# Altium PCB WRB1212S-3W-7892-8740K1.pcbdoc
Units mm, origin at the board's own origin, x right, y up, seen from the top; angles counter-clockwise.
Board outline 23.7 x 14.8 mm, 2 copper layers (Top Layer, Bottom Layer), stack 0.78 mm thick; 26 components, 17 nets, 70 pads, 31 vias.
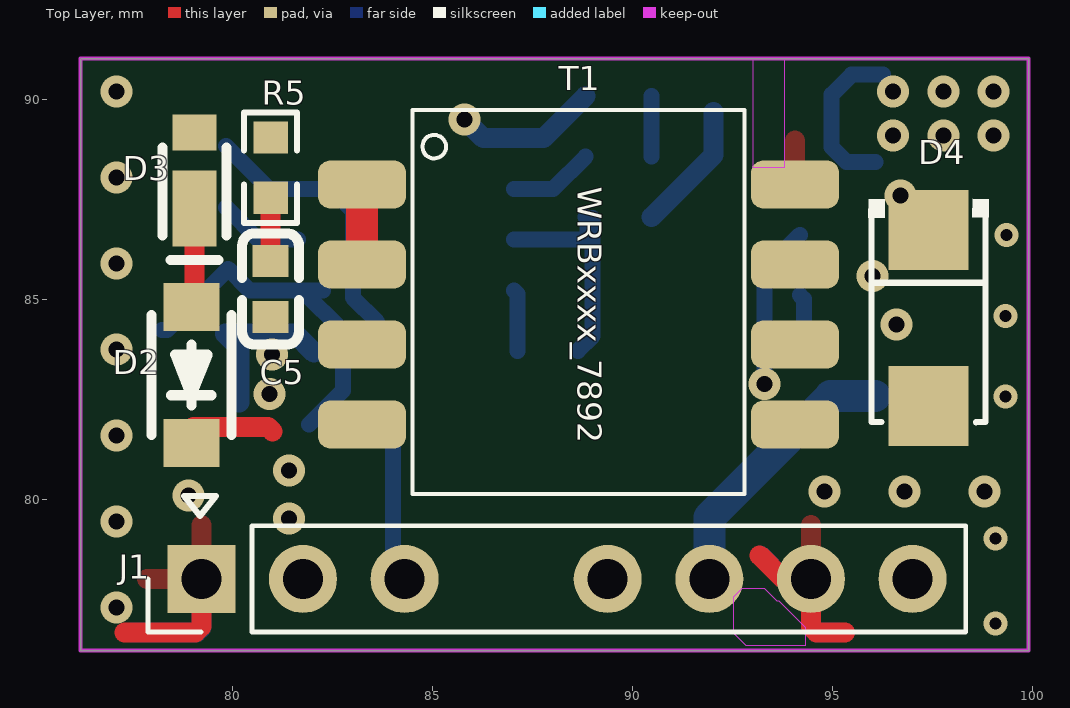
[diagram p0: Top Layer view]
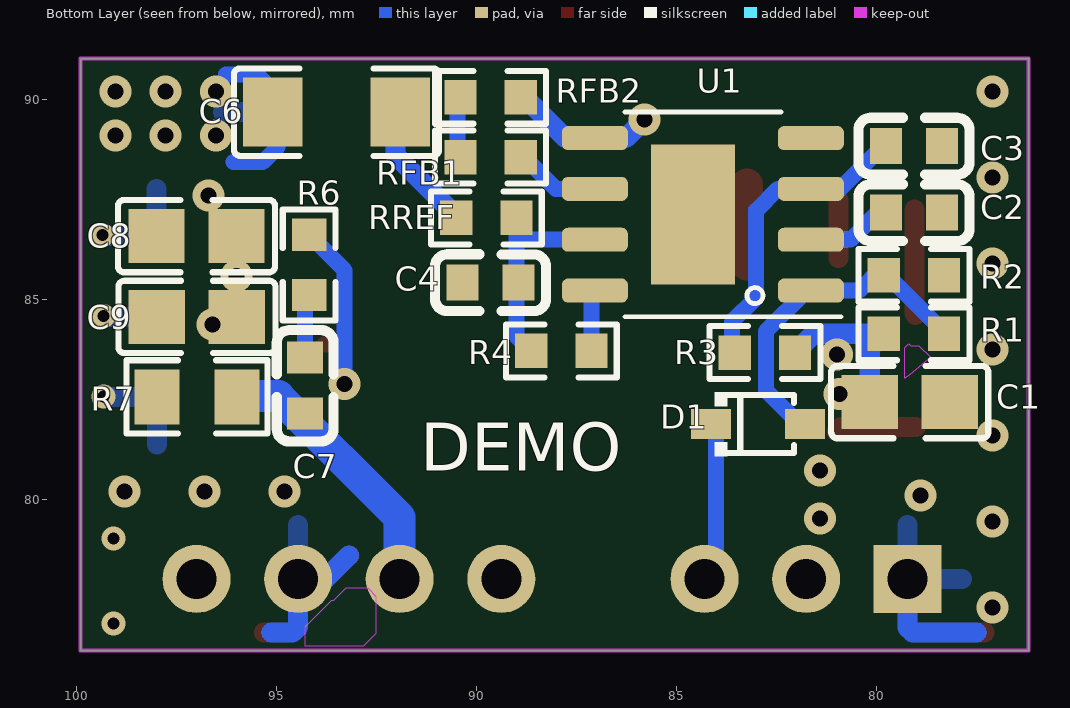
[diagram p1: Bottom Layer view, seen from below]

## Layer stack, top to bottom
Top Solder Mask Layer: solder mask 0.01, Dk 3.3
Top Layer: signal copper 0.035
Dielectric1: surface 0.71, FR4, Dk 4.5
Bottom Layer: signal copper 0.035
Bottom Solder Mask Layer: solder mask 0.01, Dk 3.3

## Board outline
76.2,91.02 99.9,91.02 99.9,76.22 76.2,76.22

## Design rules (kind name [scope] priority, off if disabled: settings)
BoardOutlineClearance safeClearance [All] p0: genericclearance=0.254 ignorepadtopadclearanceinfootprint=FALSE except(0: Arc-SplitContinuation Track-SplitContinuation SMDPad-SplitContinuation THPad-SplitContinuation Via-SplitContinuation Fill-SplitContinuation Poly-SplitContinuation Region-SplitContinuation Text-SplitContinuation)
BoardOutlineClearance Plane_innerPlane [All] p0: genericclearance=0.254 ignorepadtopadclearanceinfootprint=FALSE except(0: Arc-SplitContinuation Track-SplitContinuation SMDPad-SplitContinuation THPad-SplitContinuation Via-SplitContinuation Fill-SplitContinuation Poly-SplitContinuation Region-SplitContinuation Text-SplitContinuation)
BoardOutlineClearance Copper_CopperRegion [All] p0: genericclearance=0.254 ignorepadtopadclearanceinfootprint=FALSE except(0: Arc-SplitContinuation Track-SplitContinuation SMDPad-SplitContinuation THPad-SplitContinuation Via-SplitContinuation Fill-SplitContinuation Poly-SplitContinuation Region-SplitContinuation Text-SplitContinuation)
BoardOutlineClearance Copper_CopperRegion1 [All] p0: genericclearance=0.254 ignorepadtopadclearanceinfootprint=FALSE except(0: Arc-SplitContinuation Track-SplitContinuation SMDPad-SplitContinuation THPad-SplitContinuation Via-SplitContinuation Fill-SplitContinuation Poly-SplitContinuation Region-SplitContinuation Text-SplitContinuation)
BoardOutlineClearance Copper_CopperRegion2 [All] p0: genericclearance=0.254 ignorepadtopadclearanceinfootprint=FALSE except(0: Arc-SplitContinuation Track-SplitContinuation SMDPad-SplitContinuation THPad-SplitContinuation Via-SplitContinuation Fill-SplitContinuation Poly-SplitContinuation Region-SplitContinuation Text-SplitContinuation)
BoardOutlineClearance Copper_CopperRegion3 [All] p0: genericclearance=0.254 ignorepadtopadclearanceinfootprint=FALSE except(0: Arc-SplitContinuation Track-SplitContinuation SMDPad-SplitContinuation THPad-SplitContinuation Via-SplitContinuation Fill-SplitContinuation Poly-SplitContinuation Region-SplitContinuation Text-SplitContinuation)
BoardOutlineClearance Copper_CopperRegion4 [All] p0: genericclearance=0.254 ignorepadtopadclearanceinfootprint=FALSE except(0: Arc-SplitContinuation Track-SplitContinuation SMDPad-SplitContinuation THPad-SplitContinuation Via-SplitContinuation Fill-SplitContinuation Poly-SplitContinuation Region-SplitContinuation Text-SplitContinuation)
BoardOutlineClearance Copper_CopperRegion5 [All] p0: genericclearance=0.254 ignorepadtopadclearanceinfootprint=FALSE except(0: Arc-SplitContinuation Track-SplitContinuation SMDPad-SplitContinuation THPad-SplitContinuation Via-SplitContinuation Fill-SplitContinuation Poly-SplitContinuation Region-SplitContinuation Text-SplitContinuation)
BoardOutlineClearance Copper_CopperRegion6 [All] p0: genericclearance=0.254 ignorepadtopadclearanceinfootprint=FALSE except(0: Arc-SplitContinuation Track-SplitContinuation SMDPad-SplitContinuation THPad-SplitContinuation Via-SplitContinuation Fill-SplitContinuation Poly-SplitContinuation Region-SplitContinuation Text-SplitContinuation)
BoardOutlineClearance Copper_CopperRegion7 [All] p0: genericclearance=0.254 ignorepadtopadclearanceinfootprint=FALSE except(0: Arc-SplitContinuation Track-SplitContinuation SMDPad-SplitContinuation THPad-SplitContinuation Via-SplitContinuation Fill-SplitContinuation Poly-SplitContinuation Region-SplitContinuation Text-SplitContinuation)
BoardOutlineClearance Copper_CopperRegion8 [All] p0: genericclearance=0.254 ignorepadtopadclearanceinfootprint=FALSE except(0: Arc-SplitContinuation Track-SplitContinuation SMDPad-SplitContinuation THPad-SplitContinuation Via-SplitContinuation Fill-SplitContinuation Poly-SplitContinuation Region-SplitContinuation Text-SplitContinuation)
BoardOutlineClearance Copper_CopperRegion9 [All] p0: genericclearance=0.254 ignorepadtopadclearanceinfootprint=FALSE except(0: Arc-SplitContinuation Track-SplitContinuation SMDPad-SplitContinuation THPad-SplitContinuation Via-SplitContinuation Fill-SplitContinuation Poly-SplitContinuation Region-SplitContinuation Text-SplitContinuation)
BoardOutlineClearance Copper_CopperRegion10 [All] p0: genericclearance=0.254 ignorepadtopadclearanceinfootprint=FALSE except(0: Arc-SplitContinuation Track-SplitContinuation SMDPad-SplitContinuation THPad-SplitContinuation Via-SplitContinuation Fill-SplitContinuation Poly-SplitContinuation Region-SplitContinuation Text-SplitContinuation)
BoardOutlineClearance Copper_CopperRegion11 [All] p0: genericclearance=0.254 ignorepadtopadclearanceinfootprint=FALSE except(0: Arc-SplitContinuation Track-SplitContinuation SMDPad-SplitContinuation THPad-SplitContinuation Via-SplitContinuation Fill-SplitContinuation Poly-SplitContinuation Region-SplitContinuation Text-SplitContinuation)
BoardOutlineClearance Copper_CopperRegion12 [All] p0: genericclearance=0.254 ignorepadtopadclearanceinfootprint=FALSE except(0: Arc-SplitContinuation Track-SplitContinuation SMDPad-SplitContinuation THPad-SplitContinuation Via-SplitContinuation Fill-SplitContinuation Poly-SplitContinuation Region-SplitContinuation Text-SplitContinuation)
BoardOutlineClearance Copper_CopperRegion13 [All] p0: genericclearance=0.254 ignorepadtopadclearanceinfootprint=FALSE except(0: Arc-SplitContinuation Track-SplitContinuation SMDPad-SplitContinuation THPad-SplitContinuation Via-SplitContinuation Fill-SplitContinuation Poly-SplitContinuation Region-SplitContinuation Text-SplitContinuation)
BoardOutlineClearance otherClearance [All] p0: genericclearance=0.254 ignorepadtopadclearanceinfootprint=FALSE except(0: Arc-SplitContinuation Track-SplitContinuation SMDPad-SplitContinuation THPad-SplitContinuation Via-SplitContinuation Fill-SplitContinuation Poly-SplitContinuation Region-SplitContinuation Text-SplitContinuation)
Clearance safeClearance [All] p1: gap=0.178 ignorepadtopadclearanceinfootprint=FALSE
Clearance Plane_innerPlane [All] p1: gap=0.178 ignorepadtopadclearanceinfootprint=FALSE
Clearance Copper_CopperRegion [All] p1: gap=0.178 ignorepadtopadclearanceinfootprint=FALSE
Clearance Copper_CopperRegion1 [All] p1: gap=0.178 ignorepadtopadclearanceinfootprint=FALSE
Clearance Copper_CopperRegion2 [All] p1: gap=0.178 ignorepadtopadclearanceinfootprint=FALSE
Clearance Copper_CopperRegion3 [All] p1: gap=0.178 ignorepadtopadclearanceinfootprint=FALSE
Clearance Copper_CopperRegion4 [All] p1: gap=0.178 ignorepadtopadclearanceinfootprint=FALSE
Clearance Copper_CopperRegion5 [All] p1: gap=0.178 ignorepadtopadclearanceinfootprint=FALSE
Clearance Copper_CopperRegion6 [All] p1: gap=0.178 ignorepadtopadclearanceinfootprint=FALSE
Clearance Copper_CopperRegion7 [All] p1: gap=0.178 ignorepadtopadclearanceinfootprint=FALSE
Clearance Copper_CopperRegion8 [All] p1: gap=0.178 ignorepadtopadclearanceinfootprint=FALSE
Clearance Copper_CopperRegion9 [All] p1: gap=0.178 ignorepadtopadclearanceinfootprint=FALSE
Clearance Copper_CopperRegion10 [All] p1: gap=0.178 ignorepadtopadclearanceinfootprint=FALSE
Clearance Copper_CopperRegion11 [All] p1: gap=0.178 ignorepadtopadclearanceinfootprint=FALSE
Clearance Copper_CopperRegion12 [All] p1: gap=0.178 ignorepadtopadclearanceinfootprint=FALSE
Clearance Copper_CopperRegion13 [All] p1: gap=0.178 ignorepadtopadclearanceinfootprint=FALSE
Clearance otherClearance [All] p1: gap=0.178 ignorepadtopadclearanceinfootprint=FALSE
DiffPairsRouting differentialPair [All] p1: maxuncoupledlength=10 minlimit=5.9843 maxlimit=Infinity mostfreqgap=5.9843 toplayer_minwidth=5 toplayer_prefwidth=10 toplayer_maxwidth=100 bottomlayer_minwidth=5 bottomlayer_prefwidth=10 bottomlayer_maxwidth=100
PasteMaskExpansion Common [All] p1: expansion=0
PlaneConnect innerPlane [All] p1: planeconnectstyle=Relief reliefexpansion=0.508 reliefentries=4 reliefconductorwidth=0.254 reliefairgap=0.254
PolygonConnect CopperRegion [All] p1: connectstyle=Relief reliefentries=4 reliefconductorwidth=19.685 polygonreliefangle="90 Angle" airgapwidth=19.685
PolygonConnect CopperRegion1 [All] p1: connectstyle=Relief reliefentries=4 reliefconductorwidth=0 polygonreliefangle="90 Angle" airgapwidth=0.9843
PolygonConnect CopperRegion2 [All] p1: connectstyle=Direct reliefentries=4 reliefconductorwidth=10 polygonreliefangle="90 Angle" airgapwidth=10
PolygonConnect CopperRegion3 [All] p1: connectstyle=Relief reliefentries=4 reliefconductorwidth=19.685 polygonreliefangle="90 Angle" airgapwidth=19.685
PolygonConnect CopperRegion4 [All] p1: connectstyle=Direct reliefentries=4 reliefconductorwidth=10 polygonreliefangle="90 Angle" airgapwidth=10
PolygonConnect CopperRegion5 [All] p1: connectstyle=Direct reliefentries=4 reliefconductorwidth=10 polygonreliefangle="90 Angle" airgapwidth=10
PolygonConnect CopperRegion6 [All] p1: connectstyle=Direct reliefentries=4 reliefconductorwidth=10 polygonreliefangle="90 Angle" airgapwidth=10
PolygonConnect CopperRegion7 [All] p1: connectstyle=Direct reliefentries=4 reliefconductorwidth=10 polygonreliefangle="90 Angle" airgapwidth=10
PolygonConnect CopperRegion8 [All] p1: connectstyle=Direct reliefentries=4 reliefconductorwidth=10 polygonreliefangle="90 Angle" airgapwidth=10
PolygonConnect CopperRegion9 [All] p1: connectstyle=Relief reliefentries=4 reliefconductorwidth=19.685 polygonreliefangle="90 Angle" airgapwidth=19.685
PolygonConnect CopperRegion10 [All] p1: connectstyle=Direct reliefentries=4 reliefconductorwidth=10 polygonreliefangle="90 Angle" airgapwidth=10
PolygonConnect CopperRegion11 [All] p1: connectstyle=Relief reliefentries=4 reliefconductorwidth=19.685 polygonreliefangle="90 Angle" airgapwidth=19.685
PolygonConnect CopperRegion12 [All] p1: connectstyle=Direct reliefentries=4 reliefconductorwidth=10 polygonreliefangle="90 Angle" airgapwidth=10
PolygonConnect CopperRegion13 [All] p1: connectstyle=Direct reliefentries=4 reliefconductorwidth=10 polygonreliefangle="90 Angle" airgapwidth=10
RoutingVias viaSize [All] p1: viastyle="Through Hole" holewidth=12.0078 minholewidth=11.811 maxholewidth=236.1812 width=12.0078 minwidth=11.811 maxwidth=236.1812
SolderMaskExpansion Common [All] p1: useseparateexpansions=TRUE expansion=0 expansionbottom=0
Width trackWidth [All] p1: maxlimit=100 minlimit=5 preferedwidth=10

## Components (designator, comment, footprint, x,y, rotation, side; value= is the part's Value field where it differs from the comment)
C1 "" C0805 79.17,82.43 r180 bottom
C2 "" C0603 79.065,87.165 r0 bottom
C3 "" C0603 79.065,88.83 r180 bottom
C4 "" C0603 89.65,85.416 r180 bottom
C5 "" C0603 80.95,85.26 r270 top
C6 "" C1206 93.5,89.68 r180 bottom
C7 "" C0603 94.285,82.84 r270 bottom
C8 "" C0805 97,86.58 r0 bottom
C9 "" C0805 96.99,84.56 r0 bottom
D1 "" SOD-323_L1.8-W1.3-LS2.5-RD 82.96,81.88 r180 bottom
D2 "" SOD-123_L2.8-W1.8-LS3.9-FD 78.97,83.11 r270 top
D3 "" SOD-323HE_L1.9-W1.3-LS2.5-RD 79.05,88.22 r90 top
D4 "" SMA_L4.3-W2.6-LS5.2-RD 97.4,84.53 r270 top
J1 "" ? 79.22,78.01 r90 top
R1 "" R0603 79.065,84.137 r0 bottom
R2 "" R0603 79.065,85.601 r0 bottom
R3 "" R0603 82.79,83.67 r180 bottom
R4 "" R0603 87.88,83.71 r180 bottom
R5 "" R0603 80.95,88.29 r90 top
R6 "" R0603 94.185,85.86 r90 bottom
R7 "" R0805 96.99,82.56 r0 bottom
RFB1 "" R0603 89.65,88.556 r180 bottom
RFB2 "" R0603 89.65,90.05 r0 bottom
RREF "" R0603 89.755,87.036 r180 bottom
T1 "" "coileasy:SMD-8P, 11.55x9.6, ER9.5 4+4" 88.652,84.93 r0 top
U1 "CMP7892" coileasy:ESOP-8 84.34,87.125 r0 bottom

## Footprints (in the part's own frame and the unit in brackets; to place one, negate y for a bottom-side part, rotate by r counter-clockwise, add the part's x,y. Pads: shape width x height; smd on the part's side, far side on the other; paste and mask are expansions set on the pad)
C0603 [mm]
  rect 0.8x0.9 smd: 1(-0.7,0) 2(0.7,0)
  silkscreen extent -1.39,-0.71 1.39,0.71
C0805 [mm]
  rect 1.41x1.35 smd: 1(-1,0) 2(1,0)
  silkscreen extent -1.96,-0.9 1.96,0.9
C1206 [mm]
  rect 1.485x1.728 smd: 1(-1.593,0) 2(1.593,0)
  silkscreen extent -2.56,-1.09 2.56,1.09
coileasy:ESOP-8 [mm]
  rrect50% 1.65x0.6 smd: 1(-2.7,1.905) 2(-2.7,0.635) 3(-2.7,-0.635) 4(-2.7,-1.905) 5(2.7,-1.905) 6(2.7,-0.635) 7(2.7,0.635) 8(2.7,1.905)
  rect 2.1x3.5 smd: 9(0.25,0)
  silkscreen extent -3.45,-2.56 1.95,2.56
"coileasy:SMD-8P, 11.55x9.6, ER9.5 4+4" [mm]
  rrect50% 2.2x1.2 smd: 1(-5.412,2.94) 2(-5.412,0.94) 3(-5.412,-1.06) 4(-5.412,-3.06) 5(5.413,-3.06) 6(5.413,-1.06) 7(5.413,0.94) 8(5.413,2.94)
  silkscreen extent -4.15,-4.8 4.15,4.8
R0603 [mm]
  rect 0.806x0.864 smd: 1(-0.753,0) 2(0.753,0)
  silkscreen extent -1.39,-0.66 1.39,0.66
R0805 [mm]
  rect 1.133x1.377 smd: 1(-1,0) 2(1,0)
  silkscreen extent -1.76,-0.92 1.76,0.92
SMA_L4.3-W2.6-LS5.2-RD [mm]
  rect 2x2 smd: 1(-2.2,0) 2(2.2,0)
  silkscreen extent -2.98,-1.5 2.6,1.5
SOD-123_L2.8-W1.8-LS3.9-FD [mm]
  rect 1.2x1.4 smd: 1(-1.7,0) 2(1.7,0)
  silkscreen extent -1.5,-1 1.5,1
SOD-323_L1.8-W1.3-LS2.5-RD [mm]
  rect 1x0.75 smd: 1(-1.173,0) 2(1.173,0)
  silkscreen extent -1.08,-0.8 0.9,0.8
SOD-323HE_L1.9-W1.3-LS2.5-RD [mm]
  rect 1.9x1.1 smd: 1(-0.951,0)
  rect 0.9x1.1 smd: 2(0.951,0)
  silkscreen extent -2.23,-0.8 0.58,0.8
? [mm]
  rect 1.7x1.7 hole 1: 1(0,0)
  round 1.7 hole 1: 2(0,-2.54) 3(0,-5.08) 5(0,-10.16) 6(0,-12.7) 7(0,-15.24) 8(0,-17.78)
  silkscreen extent -1.33,-19.11 1.33,1.33

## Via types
v1: diameter 0.8, hole 0.4, Top Layer to Bottom Layer, 26 vias
v2: diameter 0.6, hole 0.3, Top Layer to Bottom Layer, 5 vias

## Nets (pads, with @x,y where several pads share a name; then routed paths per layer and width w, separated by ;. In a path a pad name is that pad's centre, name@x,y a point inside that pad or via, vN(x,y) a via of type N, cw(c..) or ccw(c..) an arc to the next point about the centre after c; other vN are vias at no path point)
$1N2: D4.2 R6.2 T1.5 T1.6 | length 4.4
  Top Layer w0.4: T1.6@93.52,83.87 T1.6@93.815,83.87
  Bottom Layer w0.4: v1(93.296,82.88) 93.296,85.724 R6.2
$1N3: D2.1 D3.1 | length 2.6
  Top Layer w0.5: D2.1@79.02,84.61 79.05,84.64 D3.1@79.05,87.245
$1N9: C5.1 R5.1 | length 1.5
  Top Layer w0.5: C5.1@80.95,86.035 R5.1@80.95,87.485
$1N15: D3.2 R5.2 RFB2.1 T1.1 T1.2 U1.5 | length 5.7
  Top Layer w0.8: T1.2 T1.1
  Bottom Layer w0.5: v1(85.8,89.5) 86.27,89.03 U1.5 87.775,89.03 RFB2.1@88.825,90.08
$1N16: C2.2 U1.2 | length 2.1
  Bottom Layer w0.4: C2.2@79.84,87.297 80.647,86.49 U1.2
$1N17: RFB1.2 U1.6 | length 2.1
  Bottom Layer w0.4: U1.6 88.017,87.76 RFB1.2@88.825,88.568
$1N18: C3.1 R3.1 U1.3 | length 7.6
  Bottom Layer w0.4: C3.1@79.84,88.83 80.91,87.76 U1.3 82.465,87.76 83.01,87.215 83.01,85.04 83.615,84.435 R3.1@83.615,83.67
$1N20: D1.2 R1.1 R2.2 U1.1 | length 9
  Bottom Layer w0.4: R1.1@78.24,84.23 78.357,84.23 79.89,85.763 80.433,85.22 U1.1 U1.1@81.745,85.22 ; D1.2@81.91,81.87 82.766,82.726 82.766,84.199 U1.1@81.745,85.22 ; U1.1@82.26,85.22 U1.1@81.745,85.22
$1N26: C4.2 R4.1 RREF.2 U1.7 | length 5.9
  Bottom Layer w0.4: U1.7 88.865,86.49 88.875,86.48 88.875,87.005 RREF.2@88.825,87.055 ; R4.1 89.002,84.078 RREF.2
$1N33: RFB1.1 RFB2.2 | length 1.5
  Bottom Layer w0.4: RFB1.1@90.475,88.568 RFB2.2@90.475,90.08
$1N478: C7.1 R6.1 | length 1.6
  Bottom Layer w0.4: R6.1 94.285,85.006 C7.1
$1N3750: R4.2 U1.8 | length 1.5
  Bottom Layer w0.4: U1.8 87.127,85.133 R4.2
CTRL: D1.1 J1.3 | length 4
  Bottom Layer w0.4: D1.1@84.01,81.87 84.01,78.27 J1.3@84.3,77.98
GND1: C1.2 C2.1 C3.2 C4.1 C6.2 J1.1 R2.1 RREF.1 U1.4 U1.9 | length 9.4
  Top Layer w0.5: 77.3,76.671 79.071,76.671 79.22,76.82 J1.1@79.22,77.98
  Bottom Layer w0.5: 77.5,76.671 79.1,76.671 79.22,76.791 J1.1@79.22,77.98 ; RREF.1@90.475,87.055 92.025,88.605 C6.2@92.025,89.68
  other v1: 77.1,77.3 77.1,79.45 78.9,80.1 77.1,81.6 77.1,83.75 77.1,85.9 77.1,88.05 77.1,90.2
GND2: C6.1 C8.2 C9.2 J1.7 R7.2 T1.7 T1.8 | length 11.1
  Top Layer w0.5: 93.18,78.6 93.77,78.01 J1.7 94.46,76.808 94.597,76.671 95.313,76.671
  Bottom Layer w0.4: 96.08,88.43 95.35,88.43 94.975,88.805 94.975,90.115 95.48,90.62 96.26,90.62
  Bottom Layer w0.5: 93.19,78.6 93.78,78.01 J1.7 94.46,76.808 94.597,76.671 95.12,76.671
  other v1: 94.8,80.2 96.8,80.2 98.8,80.2 96.51,89.1 97.77,89.1 99.03,89.1 96.51,90.2 97.77,90.2 99.03,90.2
  other v2: 99.074,76.9 99.074,79.02 99.329,82.568 99.329,84.586 99.348,86.604
VIN: C1.1 C5.2 D2.2 J1.2 R1.2 R3.2 T1.3 T1.4 | length 6.3
  Top Layer w0.5: D2.2@79.02,81.81 80.89,81.81 81,81.7
  Bottom Layer w0.508: C1.1 80.17,83.785 R1.2 81.57,84.137 R3.2
  other v1: 81.41,79.52 81.41,80.72 80.93,82.63 80.99,83.62
VO: C7.2 C8.1 C9.1 D4.1 J1.6 R7.1 | length 7
  Bottom Layer w0.8: J1.6@91.92,77.95 91.92,79.545 94.955,82.58 R7.1@96.067,82.58
  other v1: 96.596,84.377 96,85.58 96.698,87.602
pads on no net: J1.5 J1.8

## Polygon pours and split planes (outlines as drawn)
GND1 on Bottom Layer (solid, remove dead copper, pour order 26): 83.54,85.057 83.54,86.135 85.63,86.135 85.63,85.379 85.623,85.372 85.623,82.873 89.373,82.873 89.9,83.4 89.9,87.6 90.781,87.6 90.901,87.481 90.901,82.501 90.4,82 84.705,82 84.552,82.153 84.552,84.1 84.249,84.403 84.195,84.403
GND1 on Top Layer (solid, remove dead copper, pour order 0): 76.2,80 76.2,91 78,91 78,80.9 78.1,80.8 80.1,80.8 80.1,80
GND1 on Top Layer (solid, remove dead copper, pour order 2): 76.2,80.3 80.1,80.3 80.1,76.2 76.2,76.2
GND1 on Bottom Layer (solid, remove dead copper, pour order 16): 76.2,80.3 80.1,80.3 80.1,76.2 76.2,76.2
GND2 on Top Layer (solid, remove dead copper, pour order 4): 95.2,85.3 95.2,88.24 95.8,88.24 95.8,90.8 93,90.8 93,85.3
GND2 on Bottom Layer (solid, remove dead copper, pour order 18): 94.4,88.225 94.4,91 99.9,91 99.9,76.2 92.9,76.2 92.9,81.2 97.475,81.2 97.475,88.225
VO on Bottom Layer (solid, remove dead copper, pour order 20): 97.25,81.83 97.25,87.98 95.33,87.98 95.33,81.83
VO on Top Layer (solid, remove dead copper, pour order 6): 95.35,83.83 95.35,87.98 98.8,87.98 98.8,83.83
$1N2 on Top Layer (solid, remove dead copper, pour order 8): 92.9,81.43 92.9,83.63 98.8,83.63 98.8,81.43
$1N15 on Top Layer (solid, remove dead copper, pour order 10): 78.45,89.93 86.35,89.93 86.35,88.63 84.4,88.63 84.4,87.23 82.6,87.23 82.6,88.68 78.45,88.68
GND2 on Top Layer (solid, remove dead copper, pour order 12): 93,85.53 93,90.98 99.9,90.98 99.9,76.2 92.9,76.2
GND1 on Bottom Layer (solid, remove dead copper, pour order 22): 80.1,80 80.1,88.7 82.4,88.7 83.1,88 85.2,88 85.3,88.1 85.3,91 76.2,91 76.2,80
VIN on Bottom Layer (solid, remove dead copper, pour order 24): 80.4,76.3 80.4,81.5 79.5,81.5 79.5,84.6 79.6,84.7 82.2,84.7 82.6,84.3 82.6,76.2 80.5,76.2
VIN on Top Layer (solid, remove dead copper, pour order 14): 82.6,76.2 82.6,81 84.4,81 84.4,84.5 80.4,84.5 80.4,76.2 80.5,76.2

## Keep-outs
Top Layer:
  region: 93,88.3 93.8,88.3 93.8,91 93,91
  region: 92.737,77.772 93.298,77.772 93.604,77.466 93.655,77.466 94.318,76.803 94.318,76.344 92.839,76.344 92.533,76.65 92.533,77.568
Bottom Layer:
  region: 78.942,83.842 78.648,83.548 79.173,83.11 79.299,83.026 79.299,83.791 79.197,83.893 79.146,83.842
  region: 92.712,77.772 93.273,77.772 93.579,77.466 93.63,77.466 94.293,76.803 94.293,76.344 92.814,76.344 92.508,76.65 92.508,77.568
Board Outline Layer:
  the board outline again, w0.1

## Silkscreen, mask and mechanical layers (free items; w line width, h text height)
Top Silkscreen Layer:
  lines w0.15: 78.79,80.083 79.59,80.083 79.19,79.583 78.79,80.083
  text "WRBxxxx_7892" at 88.632,87.82 h0.6 r270
Bottom Silkscreen Layer:
  text "DEMO" at 91.41,80.71 h1.2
